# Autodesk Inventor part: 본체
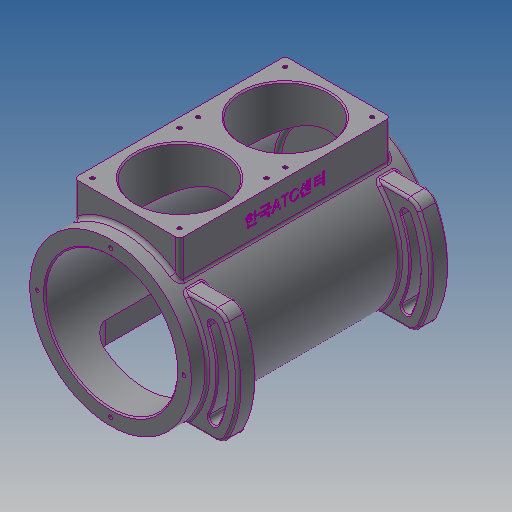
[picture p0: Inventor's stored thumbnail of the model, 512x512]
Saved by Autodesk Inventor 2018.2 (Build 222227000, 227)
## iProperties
Created: 2016-11
Part Number: 본체
Material: 알루미늄 6061
Document SubType Name: Modeling
Designer: mduedu
Density: 2.71 g/cm^3
Appearance: 기본값
Mass: 2446.35 g
Surface Area: 1767.22 cm^2
Volume: 902.713 cm^3
Author: mduedu
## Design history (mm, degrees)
sketch "스케치1"
  geometry: C1 r 65 at (0, 0); 1 further point
  constraints: 1 centre point, 1 coincident
  dimensions: "d119" = 130 diameter of C1
extrude "돌출1" new body sketch "스케치1" distance "d3" = 98; taper "d4" = 0 deg; dims "d132" = 97, "d133" = 0
feature "쉘1" dims "d120" = 12, "d134" = 8
node "작업 평면2"
sketch "스케치13"
  geometry: L1 (42.5, 85)-(-42.5, 85); L2 (-42.5, 85)-(-42.5, -85); L3 (-42.5, -85)-(42.5, -85); L4 (42.5, -85)-(42.5, 85); 2 further points
  constraints: 8 end point, 2 parallel, 1 horizontal, 1 midpoint, 1 perpendicular, 1 vertical alignment
  dimensions: "d122" = 170 distance of L1.end L2.end; "d124" = 85 distance of L2.end L3.end; "d125" = 85 distance from line of point (0, 0) L1 (= 0.5 x d122)
extrude "돌출11" join sketch "스케치13" stored distance "d126" = 10; taper "d127" = 0 deg
sketch "스케치14"
  geometry: L1 (65, 97)-(-65, 97) reference; C1 r 35 at (0, 42.5); 1 further point
  constraints: 1 centre point, 1 vertical alignment
  dimensions: "d128" = 70 diameter of C1; "d129" = 54.5 distance from line of C1.centre L1
extrude "돌출12" cut sketch "스케치14" stored distance "d130" = 10; taper "d131" = 0 deg
sketch "스케치15"
  geometry: C1 r 53 at (0, 0) reference; 1 further point
extrude "돌출13" cut sketch "스케치15" stored distance "d135" = 10; taper "d136" = 0 deg
chamfer "모따기1" distance "d54" = 1; stored, may be unused: second distance "d55" = 2, angle "d56" = 45 deg
sketch "스케치8"
  geometry: C1 r 30 at (0, 0); C2 r 65 at (0, 0) reference; 1 further point
  constraints: 1 centre point, 1 concentric
  dimensions: "d57" = 60 diameter of C1
extrude "돌출8" join sketch "스케치8" distance "d58" = 14; taper "d59" = 0 deg
hole "구멍3" diameter "d62" = 41; stored, may be unused: countersink angle "d66" = 90 deg, drill point angle "d68" = 0 deg; dims "d63" = 6, "d64" = 47, "d65" = 14, "d67" = 17, "d195" = 10, "d196" = 10
fillet "모깎기11" dims "d69" = 3
fillet "모깎기12" dims "d70" = 3
fillet "모깎기13" dims "d71" = 0.3
chamfer "모따기2" distance "d72" = 1; stored, may be unused: second distance "d73" = 2, angle "d74" = 45 deg
node "작업 평면3"
sketch "스케치16"
  geometry: L1 (-42.5, -80)-(47.5, -80); L2 (-42.5, -80)-(21.14, -16.36); L3 (-42.5, -80)-(21.14, -143.64); L4 (3.462, -34.038)-(34.879, -34.038); L5 (3.462, -125.962)-(34.879, -125.962); A1 r 65 centre (-42.5, -80) between (3.462, -34.038) and (3.462, -125.962) reference; A2 r 90 centre (-42.5, -80) between (34.879, -125.962) and (34.879, -34.038); A3 r 90 centre (-42.5, -80) between (34.879, -34.038) and (34.879, -125.962); A4 r 65 centre (-42.5, -80) between (3.462, -125.962) and (3.462, -34.038); 1 further point
  constraints: 11 point on circle, 10 end point, 3 centre point, 2 parallel, 2 point on line, 1 coincident, 1 horizontal
  dimensions: "d140" = 45 deg angle of L3 L1; "d141" = 45 deg angle of L2 L1; "d142" = 25 radial gap between concentric circles of A1 A2
extrude "돌출14" join sketch "스케치16" distance "d143" = 15; taper "d144" = 0 deg
sketch "스케치17"
  geometry: L1 (-42.5, -80)-(34.414, -80); L2 (-42.5, -80)-(27.208, -47.495); L3 (-42.5, -80)-(27.208, -112.505); L4 (34.879, -34.038)-(3.462, -34.038) reference; L5 (3.462, -125.962)-(34.879, -125.962) reference; A1 r 65 centre (-42.5, -80) between (3.462, -34.038) and (3.462, -125.962) reference; A2 r 76.914 centre (-42.5, -80) between (19.17, -125.962) and (19.17, -34.038); A3 r 4 centre (27.208, -47.495) between (23.582, -49.185) and (30.833, -45.804); A4 r 4 centre (27.208, -112.505) between (30.833, -114.196) and (23.582, -110.815); A5 r 80.914 centre (-42.5, -80) between (30.833, -114.196) and (30.833, -45.804); A6 r 72.914 centre (-42.5, -80) between (23.582, -110.815) and (23.582, -49.185); 1 further point
  constraints: 13 point on circle, 6 end point, 5 centre point, 5 coincident, 3 midpoint, 2 point on line, 1 equal radius, 1 horizontal
  dimensions: "d145" = 25 deg angle of L1 L3; "d146" = 25 deg angle of L2 L1; "d147" = 8 diameter of A3
extrude "돌출15" cut sketch "스케치17" stored distance "d150" = 15; taper "d151" = 0 deg
fillet "모깎기17" dims "d152" = 10
fillet "모깎기18" dims "d153" = 2
fillet "모깎기19" dims "d154" = 2
chamfer "모따기4" distance "d155" = 1; stored, may be unused: second distance "d156" = 2, angle "d157" = 45 deg
fillet "모깎기20" dims "d159" = 3
fillet "모깎기21" dims "d160" = 3
fillet "모깎기22" dims "d161" = 3
node "작업 평면4"
sketch "스케치18"
  geometry: L1 (-42.5, 70)-(42.5, 70); L2 (42.5, 70)-(42.5, -70); L3 (42.5, -70)-(-42.5, -70); L4 (-42.5, -70)-(-42.5, 70); 2 further points
  constraints: 8 end point, 2 parallel, 1 horizontal, 1 midpoint, 1 perpendicular, 1 vertical alignment
  dimensions: "d162" = 140 distance of L1.end L2.end; "d164" = 85 distance of L2.end L3.end; "d165" = 70 distance from line of point (0, 0) L1 (= 0.5 x d162)
extrude "돌출16" cut sketch "스케치18" stored distance "d166" = 15; taper "d167" = 0 deg
fillet "모깎기23" dims "d168" = 10
fillet "모깎기24" dims "d173" = 3
sketch "스케치19"
  geometry: 4 further points
  constraints: 4 other
hole "구멍6" sketch "스케치19" at (0, -59), (59, 0), (-59, 0), (0, 59) diameter "d174" = 3.242; stored, may be unused: countersink angle "d178" = 90 deg, drill point angle "d180" = 120 deg; dims "d175" = 8, "d176" = 4, "d177" = 2, "d179" = 10
sketch "스케치20"
  geometry: L1 (35, -77.5)-(-35, -77.5); L2 (-35, -77.5)-(-35, -7.5); L3 (-35, -7.5)-(35, -7.5); L4 (35, -7.5)-(35, -77.5); L5 (35, -77.5)-(-35, -7.5); L6 (-35, -77.5)-(35, -7.5); C1 r 36 at (0, -42.5) reference; 5 further points
  constraints: 12 end point, 4 coincident, 2 midpoint, 2 parallel, 1 horizontal, 1 perpendicular
  dimensions: "d181" = 70 distance of L2.end L3.end; "d182" = 70 distance of L1.end L2.end
hole "구멍7" sketch "스케치20" at (-35, -77.5), (-35, -7.5), (35, -7.5), (35, -77.5) diameter "d183" = 3.242; stored, may be unused: countersink angle "d187" = 90 deg, drill point angle "d189" = 118 deg; dims "d184" = 8, "d185" = 4, "d186" = 2, "d188" = 10
sketch "스케치21"
  geometry: L1 (164, 0)-(0, 0) reference; L2 (-3, 0)-(-3, -24.649) reference; 3 further points
  constraints: 1 midpoint, 1 vertical alignment, 1 other
  dimensions: "d190" = 15 distance from line of point (82, -15) L1; "d191" = 85 distance from line of point (82, 0) L2 (derived)
feature "엠보싱2" sketch "스케치21" dims "d3" = 98, "d4" = 0, "d119" = 130, "d132" = 97, "d133" = 0, "d192" = 0.5, "d193" = 0
node "솔리드1"
mirror "대칭5"
mirror "대칭6"
mirror "대칭7"
